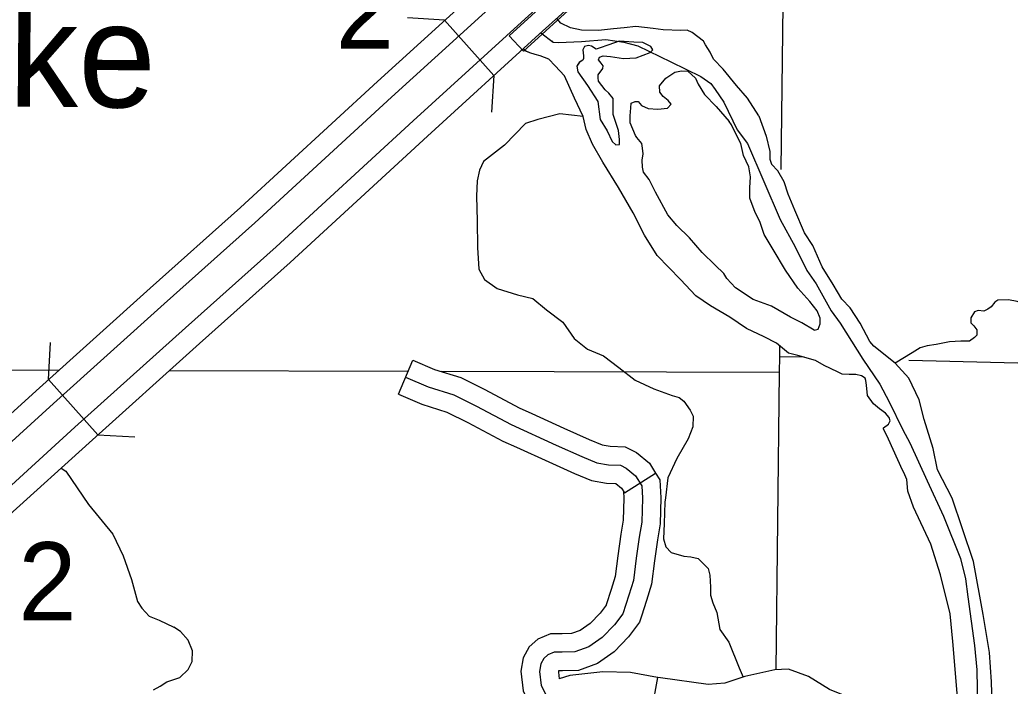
# Model space of a CAD drawing. Extents: x 8749 to 11879, y 13275 to 15339.
# Drawn here: x 10252.7 to 10333, y 13840.7 to 13894.7 of the extents above; entities that cross this region are included whole.
import ezdxf

# ---------------------------------------------------------------- set-up
doc = ezdxf.new("R2010")
doc.units = 0
for name, color, linetype in [('Level 19', 7, 'Continuous'), ('Level 2', 7, 'Continuous'), ('Level 35', 7, 'Continuous'), ('Level 37', 7, 'Continuous'), ('Level 39', 7, 'Continuous'), ('Level 4', 7, 'Continuous'), ('Level 45', 7, 'Continuous'), ('Level 5', 7, 'Continuous'), ('Level 9', 7, 'Continuous')]:
    doc.layers.add(name, color=color, linetype=linetype)

msp = doc.modelspace()

# ---------------------------------------------------------------- linework, layer by layer
at = {"layer": 'Level 19'}
msp.add_line((10293.525, 13892.125), (10292.381, 13893.383), dxfattribs=at)
for points in [[(10292.381, 13893.383), (10379.95, 13973.091)], [(10381.087, 13971.827), (10293.525, 13892.125)], [(10297.67, 13901.884), (10296.529, 13903.145), (10290.778, 13897.94), (10281.704, 13889.663), (10270.608, 13879.473), (10263.266, 13872.928), (10254.301, 13864.855), (10247.825, 13858.989), (10233.593, 13845.826)], [(10234.747, 13844.578), (10248.973, 13857.735), (10255.44, 13863.594), (10264.4, 13871.662), (10271.748, 13878.213), (10282.851, 13888.409), (10291.921, 13896.682), (10297.67, 13901.884)], [(10300.561, 13898.676), (10299.414, 13899.956), (10293.669, 13894.758), (10284.607, 13886.491), (10273.493, 13876.285), (10266.135, 13869.726), (10257.183, 13861.664), (10250.729, 13855.817), (10236.513, 13842.669)], [(10237.667, 13841.421), (10251.877, 13854.563), (10258.323, 13860.402), (10267.27, 13868.46), (10274.633, 13875.024), (10285.755, 13885.237), (10294.812, 13893.5), (10300.555, 13898.696)]]:
    msp.add_lwpolyline(points, dxfattribs=at)
at = {"layer": 'Level 2'}
for points in [[(10294.95, 13893.624), (10295.95, 13892.874), (10296.381, 13892.841), (10298.251, 13892.907), (10300.204, 13893.072), (10301.677, 13892.857), (10302.803, 13892.559), (10305.468, 13891.269), (10307.918, 13890.094), (10308.729, 13889.515), (10309.06, 13889.035), (10309.771, 13888.009), (10310.864, 13885.759), (10311.691, 13884.666), (10314.346, 13878.492)], [(10295.825, 13892.968), (10295.95, 13892.874), (10296.381, 13892.841), (10298.251, 13892.907), (10300.204, 13893.072), (10301.677, 13892.857), (10302.803, 13892.559), (10305.468, 13891.269), (10307.918, 13890.094), (10308.729, 13889.515), (10309.06, 13889.035), (10309.771, 13888.009), (10310.864, 13885.759), (10311.691, 13884.666), (10314.346, 13878.492)], [(10314.346, 13878.492), (10315.558, 13876.278), (10316.514, 13874.366), (10317.261, 13873.291), (10318.487, 13871.11), (10319.204, 13870.094), (10321.051, 13867.191), (10322.411, 13865.145), (10323.187, 13863.734), (10324.281, 13861.468), (10324.852, 13860.391), (10326.247, 13857.328), (10327.578, 13854.452), (10328.961, 13851.043), (10329.365, 13849.387), (10329.566, 13847.933), (10330.105, 13843.991), (10330.276, 13842.014), (10330.333, 13838.896)], [(10314.346, 13878.492), (10315.558, 13876.278), (10316.514, 13874.366), (10317.261, 13873.291), (10318.487, 13871.11), (10319.204, 13870.094), (10321.051, 13867.191), (10322.411, 13865.145), (10323.187, 13863.734), (10324.281, 13861.468), (10324.852, 13860.391), (10326.247, 13857.328), (10327.578, 13854.452), (10328.961, 13851.043), (10329.365, 13849.387), (10329.566, 13847.933), (10330.105, 13843.991), (10330.276, 13842.014), (10330.333, 13838.896)]]:
    msp.add_lwpolyline(points, dxfattribs=at)
at = {"layer": 'Level 35'}
for points in [[(10298.365, 13886.829), (10296.493, 13887.048), (10294.692, 13886.607), (10293.691, 13886.287), (10292.01, 13884.524), (10290.289, 13883.202), (10289.969, 13882.481), (10289.769, 13881.64), (10289.729, 13880.398), (10289.769, 13878.395), (10289.809, 13876.231), (10289.929, 13874.469), (10290.369, 13873.627), (10291.41, 13872.906), (10293.051, 13872.385), (10294.292, 13872.105), (10295.412, 13871.184), (10296.733, 13870.182), (10297.653, 13868.86), (10298.734, 13867.979), (10300.015, 13867.458), (10301.255, 13866.496), (10302.597, 13865.481)], [(10332.849, 13871.99), (10331.981, 13871.972), (10331.731, 13871.797), (10331.456, 13871.423), (10331.182, 13871.223), (10330.857, 13871.073), (10330.383, 13871.123), (10330.083, 13871.023), (10329.808, 13870.523), (10329.808, 13870.123), (10330.033, 13869.873), (10330.283, 13869.548), (10330.283, 13869.124), (10330.083, 13868.949), (10329.684, 13868.649), (10328.985, 13868.649), (10328.061, 13868.574), (10326.987, 13868.374), (10326.263, 13868.274), (10325.689, 13868.099), (10325.04, 13867.699), (10323.667, 13866.847)], [(10335.446, 13869.109), (10335.296, 13869.866), (10335.296, 13870.216), (10335.221, 13870.69), (10334.872, 13871.065), (10334.572, 13871.365), (10334.272, 13871.615), (10333.548, 13871.865), (10332.849, 13871.99)], [(10302.597, 13865.481), (10304.099, 13864.785), (10305.598, 13864.239), (10306.144, 13864.075), (10306.525, 13863.775), (10307.043, 13863.039), (10307.288, 13862.575), (10307.261, 13861.702), (10306.879, 13860.72), (10305.953, 13859.137), (10305.249, 13857.558), (10305.05, 13855.948), (10304.995, 13855.593), (10304.931, 13853.861), (10304.891, 13852.629), (10305.081, 13851.989), (10305.517, 13851.525), (10306.525, 13851.225), (10307.097, 13851.171), (10307.697, 13851.034), (10308.079, 13850.652), (10308.515, 13850.216), (10308.651, 13849.67), (10308.706, 13848.715), (10308.706, 13848.061), (10308.896, 13847.433), (10309.196, 13846.658), (10309.441, 13845.267), (10310.177, 13844.257), (10311.022, 13842.184), (10311.342, 13841.427)], [(10256.059, 13858.352), (10256.439, 13858.095), (10258.28, 13855.411), (10260.241, 13853.007), (10261.081, 13851.245), (10261.762, 13849.322), (10262.242, 13847.559), (10262.602, 13846.998), (10263.202, 13846.357), (10264.003, 13846.037), (10265.204, 13845.476)], [(10263.535, 13840.394), (10264.081, 13840.694), (10264.626, 13841.049), (10265.689, 13841.404), (10266.343, 13842.031), (10266.67, 13842.686), (10266.697, 13843.559), (10266.343, 13844.405), (10265.743, 13845.114), (10265.204, 13845.476)]]:
    msp.add_lwpolyline(points, dxfattribs=at)
at = {"layer": 'Level 39'}
for p, q in [((10287.136, 13894.655), (10284.141, 13894.828)), ((10291.126, 13890.174), (10287.136, 13894.655)), ((10291.126, 13890.174), (10290.953, 13887.179)), ((10255.032, 13865.524), (10255.193, 13868.519)), ((10255.032, 13865.524), (10259.042, 13861.06)), ((10259.042, 13861.06), (10262.038, 13860.9))]:
    msp.add_line(p, q, dxfattribs=at)
at = {"layer": 'Level 4'}
for points in [[(10314.739, 13911.435), (10314.398, 13882.543)], [(10314.281, 13868.287), (10314.277, 13867.41), (10314.27, 13866.1), (10313.992, 13842.024)]]:
    msp.add_lwpolyline(points, dxfattribs=at)
at = {"layer": 'Level 45'}
for p, q in [((10283.395, 13864.345), (10284.572, 13867.104)), ((10301.711, 13856.351), (10304.247, 13857.955)), ((10304.412, 13841.403), (10303.869, 13838.452))]:
    msp.add_line(p, q, dxfattribs=at)
for points in [[(10284.572, 13867.104), (10286.336, 13866.351), (10288.455, 13865.69), (10290.411, 13864.711), (10293.191, 13863.239), (10294.216, 13862.771)], [(10283.984, 13865.725), (10285.816, 13864.942), (10287.892, 13864.294), (10289.725, 13863.377), (10292.528, 13861.893), (10296.194, 13860.22), (10298.269, 13859.303), (10299.482, 13858.79), (10300.425, 13858.628), (10301.396, 13858.601), (10301.854, 13858.358), (10302.609, 13857.738), (10303.121, 13856.928), (10303.175, 13855.93), (10303.121, 13853.987), (10302.905, 13852.773), (10302.663, 13851.046), (10302.447, 13849.26), (10302.069, 13848.073), (10301.584, 13846.562), (10300.91, 13845.645), (10299.913, 13844.619), (10298.835, 13843.864), (10297.703, 13843.459), (10296.679, 13843.432), (10296.032, 13843.432), (10295.52, 13843.216), (10295.196, 13842.92), (10294.954, 13842.488), (10294.846, 13841.867), (10294.981, 13840.734), (10295.613, 13839.466)], [(10283.395, 13864.345), (10285.297, 13863.533), (10287.329, 13862.899), (10289.038, 13862.043), (10291.865, 13860.547), (10292.971, 13860.042)], [(10294.216, 13862.771), (10296.808, 13861.589), (10298.864, 13860.68), (10299.906, 13860.239), (10300.574, 13860.125), (10301.788, 13860.091), (10302.69, 13859.613), (10303.747, 13858.743), (10304.247, 13857.955)], [(10292.971, 13860.042), (10295.579, 13858.852), (10297.674, 13857.926), (10299.058, 13857.341), (10300.277, 13857.132), (10301.003, 13857.112), (10301.018, 13857.104), (10301.47, 13856.732), (10301.711, 13856.351)], [(10304.247, 13857.955), (10304.597, 13857.4), (10304.676, 13855.95), (10304.617, 13853.835), (10304.387, 13852.538), (10304.15, 13850.852), (10303.919, 13848.94), (10303.498, 13847.617), (10303.091, 13846.348)], [(10301.644, 13856.457), (10301.673, 13855.91), (10301.624, 13854.14), (10301.423, 13853.009), (10301.175, 13851.241), (10300.974, 13849.58), (10300.641, 13848.53), (10300.235, 13847.266)], [(10300.235, 13847.266), (10300.231, 13847.253), (10299.763, 13846.616), (10298.936, 13845.767), (10298.14, 13845.208), (10297.424, 13844.952), (10296.659, 13844.932), (10295.729, 13844.932), (10294.697, 13844.498), (10294.006, 13843.863), (10293.52, 13842.998), (10293.33, 13841.908), (10293.522, 13840.298), (10293.738, 13839.865)], [(10303.091, 13846.348), (10302.938, 13845.871), (10302.058, 13844.673), (10300.89, 13843.472), (10299.53, 13842.52), (10297.982, 13841.966), (10296.698, 13841.932), (10296.38, 13841.932), (10296.361, 13841.827), (10296.426, 13841.279)], [(10304.412, 13841.403), (10302.2, 13841.81), (10299.959, 13841.84), (10297.304, 13841.545), (10296.426, 13841.279)], [(10314.442, 13842.042), (10313.905, 13842.021), (10312.929, 13841.8), (10311.485, 13841.46), (10309.869, 13840.929), (10308.513, 13840.822), (10304.638, 13841.361), (10304.413, 13841.403)], [(10324.659, 13839.378), (10320.877, 13839.696), (10319.482, 13839.952), (10318.346, 13840.411), (10316.648, 13841.48), (10315.005, 13842.065), (10314.442, 13842.042)]]:
    msp.add_lwpolyline(points, dxfattribs=at)
at = {"layer": 'Level 5'}
msp.add_line((10314.277, 13867.41), (10316.286, 13867.36), dxfattribs=at)
for points in [[(10255.875, 13866.273), (10208.843, 13866.412)], [(10324.762, 13867.112), (10367.851, 13866.039)], [(10284.182, 13866.189), (10264.812, 13866.246)], [(10314.27, 13866.1), (10286.882, 13866.181)]]:
    msp.add_lwpolyline(points, dxfattribs=at)
at = {"layer": 'Level 9'}
for points in [[(10302.643, 13894.125), (10301.706, 13894.011), (10300.82, 13893.935), (10299.605, 13893.808), (10298.239, 13893.834), (10297.353, 13894.011), (10296.568, 13894.391), (10296.229, 13894.781)], [(10302.643, 13894.125), (10301.706, 13894.011), (10300.82, 13893.935), (10299.605, 13893.808), (10298.239, 13893.834), (10297.353, 13894.011), (10296.568, 13894.391), (10296.323, 13894.673)], [(10312.616, 13886.905), (10311.704, 13888.323), (10310.793, 13889.362), (10309.73, 13890.679), (10308.945, 13891.49), (10308.667, 13892.048), (10308.287, 13892.656), (10308.136, 13892.934), (10307.68, 13893.289), (10307.199, 13893.644), (10306.794, 13893.846), (10306.288, 13893.821), (10304.845, 13893.872), (10304.035, 13893.973), (10302.643, 13894.125)], [(10312.616, 13886.905), (10311.704, 13888.323), (10310.793, 13889.362), (10309.73, 13890.679), (10308.945, 13891.49), (10308.667, 13892.048), (10308.287, 13892.656), (10308.136, 13892.934), (10307.68, 13893.289), (10307.199, 13893.644), (10306.794, 13893.846), (10306.288, 13893.821), (10304.845, 13893.872), (10304.035, 13893.973), (10302.643, 13894.125)], [(10298.087, 13891.262), (10297.859, 13890.907), (10297.935, 13890.451), (10298.72, 13889.362), (10299.555, 13888.045), (10299.757, 13886.601), (10300.314, 13885.688), (10300.719, 13884.802), (10301.023, 13884.548), (10301.327, 13884.574), (10301.327, 13884.979), (10301.225, 13885.714), (10300.795, 13887.006), (10300.795, 13887.918), (10300.795, 13888.298), (10300.466, 13888.729), (10300.162, 13889.007), (10299.605, 13889.691), (10299.58, 13889.97), (10299.58, 13890.223), (10299.96, 13890.73), (10299.985, 13890.933), (10299.833, 13891.161), (10299.605, 13891.439), (10299.707, 13891.642), (10299.985, 13891.769), (10300.593, 13891.693), (10301.656, 13891.541), (10302.668, 13891.591), (10303.807, 13892.022), (10304.01, 13892.25), (10303.858, 13892.504), (10303.2, 13892.833), (10302.491, 13892.858), (10301.301, 13892.934), (10300.441, 13892.656), (10299.681, 13892.377), (10299.428, 13892.301), (10299.049, 13892.529), (10298.796, 13892.58), (10298.492, 13892.504), (10298.34, 13892.25), (10298.391, 13891.769), (10298.391, 13891.541), (10298.34, 13891.414), (10298.036, 13891.211)], [(10298.068, 13891.233), (10297.859, 13890.907), (10297.935, 13890.451), (10298.72, 13889.362), (10299.555, 13888.045), (10299.757, 13886.601), (10300.314, 13885.688), (10300.719, 13884.802), (10301.023, 13884.548), (10301.327, 13884.574), (10301.327, 13884.979), (10301.225, 13885.714), (10300.795, 13887.006), (10300.795, 13887.918), (10300.795, 13888.298), (10300.466, 13888.729), (10300.162, 13889.007), (10299.605, 13889.691), (10299.58, 13889.97), (10299.58, 13890.223), (10299.96, 13890.73), (10299.985, 13890.933), (10299.833, 13891.161), (10299.605, 13891.439), (10299.707, 13891.642), (10299.985, 13891.769), (10300.593, 13891.693), (10301.656, 13891.541), (10302.668, 13891.591), (10303.807, 13892.022), (10304.01, 13892.25), (10303.858, 13892.504), (10303.2, 13892.833), (10302.491, 13892.858), (10301.301, 13892.934), (10300.441, 13892.656), (10299.681, 13892.377), (10299.428, 13892.301), (10299.049, 13892.529), (10298.796, 13892.58), (10298.492, 13892.504), (10298.34, 13892.25), (10298.391, 13891.769), (10298.391, 13891.541), (10298.34, 13891.414), (10298.068, 13891.233)], [(10296.112, 13890.958), (10295.581, 13891.49), (10294.898, 13891.744), (10294.493, 13891.87), (10294.037, 13891.997), (10293.708, 13892.149), (10293.522, 13892.322)], [(10296.112, 13890.958), (10295.581, 13891.49), (10294.898, 13891.744), (10294.493, 13891.87), (10294.037, 13891.997), (10293.604, 13892.197)], [(10298.365, 13886.829), (10297.682, 13888.323), (10296.872, 13890.147), (10296.112, 13890.958)], [(10298.365, 13886.829), (10297.682, 13888.323), (10296.872, 13890.147), (10296.112, 13890.958)], [(10302.263, 13887.918), (10302.592, 13888.045), (10302.845, 13888.045), (10303.098, 13887.741), (10303.655, 13887.487), (10304.415, 13887.437), (10305.199, 13887.513), (10305.503, 13887.842), (10305.25, 13888.146), (10304.87, 13888.45), (10304.592, 13888.805), (10304.567, 13889.337), (10305.073, 13889.945), (10305.807, 13890.426), (10306.338, 13890.527), (10306.87, 13890.502), (10307.477, 13889.945), (10307.705, 13889.463), (10308.211, 13888.627), (10309.148, 13887.639), (10310.211, 13886.423)], [(10302.263, 13887.918), (10302.592, 13888.045), (10302.845, 13888.045), (10303.098, 13887.741), (10303.655, 13887.487), (10304.415, 13887.437), (10305.199, 13887.513), (10305.503, 13887.842), (10305.25, 13888.146), (10304.87, 13888.45), (10304.592, 13888.805), (10304.567, 13889.337), (10305.073, 13889.945), (10305.807, 13890.426), (10306.338, 13890.527), (10306.87, 13890.502), (10307.477, 13889.945), (10307.705, 13889.463), (10308.211, 13888.627), (10309.148, 13887.639), (10310.211, 13886.423)], [(10302.187, 13886.905), (10302.238, 13887.538), (10302.263, 13887.918)], [(10302.187, 13886.905), (10302.238, 13887.538), (10302.263, 13887.918)], [(10303.349, 13877.214), (10302.438, 13879.038), (10301.248, 13881.09), (10299.96, 13883.13), (10299.125, 13884.599), (10298.618, 13885.79), (10298.365, 13886.829)], [(10303.349, 13877.214), (10302.438, 13879.038), (10301.248, 13881.09), (10299.96, 13883.13), (10299.125, 13884.599), (10298.618, 13885.79), (10298.365, 13886.829)], [(10302.729, 13885.138), (10302.618, 13885.308), (10302.187, 13886.322), (10302.187, 13886.905)], [(10302.729, 13885.138), (10302.618, 13885.308), (10302.187, 13886.322), (10302.187, 13886.905)], [(10312.307, 13879.074), (10311.882, 13880.216), (10311.882, 13881.052), (10311.932, 13881.964), (10311.806, 13882.75), (10311.375, 13883.687), (10311.148, 13884.65), (10310.768, 13885.384), (10310.388, 13886.17), (10310.211, 13886.423)], [(10312.307, 13879.074), (10311.882, 13880.216), (10311.882, 13881.052), (10311.932, 13881.964), (10311.806, 13882.75), (10311.375, 13883.687), (10311.148, 13884.65), (10310.768, 13885.384), (10310.388, 13886.17), (10310.211, 13886.423)], [(10312.616, 13886.905), (10313.198, 13885.258), (10313.502, 13884.016), (10313.502, 13883.383), (10313.628, 13882.978), (10314.157, 13882.433)], [(10312.616, 13886.905), (10313.198, 13885.258), (10313.502, 13884.016), (10313.502, 13883.383), (10313.628, 13882.978), (10314.157, 13882.433)], [(10303.723, 13881.732), (10303.276, 13882.344), (10303.174, 13882.724), (10303.149, 13883.307), (10303.225, 13883.814), (10303.174, 13884.27), (10303.124, 13884.65), (10302.729, 13885.138)], [(10303.723, 13881.732), (10303.276, 13882.344), (10303.174, 13882.724), (10303.149, 13883.307), (10303.225, 13883.814), (10303.174, 13884.27), (10303.124, 13884.65), (10302.729, 13885.138)], [(10320.832, 13870.09), (10320.029, 13871.336), (10319.346, 13872.046), (10318.637, 13873.236), (10317.751, 13874.655), (10316.992, 13876.378), (10316.309, 13877.417), (10315.524, 13879.241), (10314.992, 13880.558), (10314.663, 13881.546), (10314.157, 13882.433)], [(10320.832, 13870.09), (10320.029, 13871.336), (10319.346, 13872.046), (10318.637, 13873.236), (10317.751, 13874.655), (10316.992, 13876.378), (10316.309, 13877.417), (10315.524, 13879.241), (10314.992, 13880.558), (10314.663, 13881.546), (10314.157, 13882.433)], [(10305.245, 13878.871), (10304.235, 13880.71), (10303.723, 13881.732)], [(10305.245, 13878.871), (10304.235, 13880.71), (10303.723, 13881.732)], [(10317.091, 13869.522), (10316.104, 13870.13), (10315.192, 13870.586), (10313.648, 13871.473), (10312.155, 13872.005), (10310.712, 13872.968), (10310.029, 13873.703), (10309.776, 13874.133), (10309.067, 13874.792), (10308.029, 13875.831), (10306.992, 13877.021), (10305.954, 13878.01), (10305.245, 13878.871)], [(10317.091, 13869.522), (10316.104, 13870.13), (10315.192, 13870.586), (10313.648, 13871.473), (10312.155, 13872.005), (10310.712, 13872.968), (10310.029, 13873.703), (10309.776, 13874.133), (10309.067, 13874.792), (10308.029, 13875.831), (10306.992, 13877.021), (10305.954, 13878.01), (10305.245, 13878.871)], [(10317.091, 13869.522), (10317.42, 13869.624), (10317.597, 13870.054), (10317.597, 13870.51), (10317.344, 13871.093), (10316.736, 13871.853), (10315.775, 13872.943), (10314.787, 13874.387), (10313.775, 13876.059), (10313.041, 13877.275), (10312.687, 13878.339), (10312.307, 13879.074)], [(10317.091, 13869.522), (10317.42, 13869.624), (10317.597, 13870.054), (10317.597, 13870.51), (10317.344, 13871.093), (10316.736, 13871.853), (10315.775, 13872.943), (10314.787, 13874.387), (10313.775, 13876.059), (10313.041, 13877.275), (10312.687, 13878.339), (10312.307, 13879.074)], [(10315.01, 13867.658), (10314.053, 13868.484), (10313.041, 13868.99), (10311.624, 13869.674), (10310.257, 13870.586), (10308.687, 13871.498), (10307.498, 13872.309), (10306.257, 13873.627), (10304.384, 13875.577), (10303.349, 13877.214)], [(10315.01, 13867.658), (10314.053, 13868.484), (10313.041, 13868.99), (10311.624, 13869.674), (10310.257, 13870.586), (10308.687, 13871.498), (10307.498, 13872.309), (10306.257, 13873.627), (10304.384, 13875.577), (10303.349, 13877.214)], [(10327.084, 13858.226), (10326.73, 13859.956), (10326.021, 13862.287), (10325.616, 13863.883), (10324.781, 13865.631), (10323.667, 13866.847), (10321.946, 13868.24), (10321.617, 13868.62), (10320.832, 13870.09)], [(10327.084, 13858.226), (10326.73, 13859.956), (10326.021, 13862.287), (10325.616, 13863.883), (10324.781, 13865.631), (10323.667, 13866.847), (10321.946, 13868.24), (10321.617, 13868.62), (10320.832, 13870.09)], [(10324.249, 13858.2), (10323.135, 13860.691), (10322.705, 13861.527), (10322.73, 13861.628), (10323.11, 13861.907), (10323.262, 13862.185), (10323.186, 13862.464), (10322.882, 13862.819), (10322.401, 13863.148), (10321.895, 13863.553), (10321.414, 13864.238), (10321.338, 13865.074), (10321.288, 13865.454), (10321.237, 13865.631), (10320.933, 13865.834), (10320.478, 13865.935), (10319.946, 13865.935), (10319.364, 13865.96), (10318.984, 13866.163), (10317.921, 13866.67), (10317.212, 13867.075), (10315.77, 13867.48), (10315.01, 13867.658)], [(10324.249, 13858.2), (10323.135, 13860.691), (10322.705, 13861.527), (10322.73, 13861.628), (10323.11, 13861.907), (10323.262, 13862.185), (10323.186, 13862.464), (10322.882, 13862.819), (10322.401, 13863.148), (10321.895, 13863.553), (10321.414, 13864.238), (10321.338, 13865.074), (10321.288, 13865.454), (10321.237, 13865.631), (10320.933, 13865.834), (10320.478, 13865.935), (10319.946, 13865.935), (10319.364, 13865.96), (10318.984, 13866.163), (10317.921, 13866.67), (10317.212, 13867.075), (10315.77, 13867.48), (10315.01, 13867.658)], [(10328.603, 13841.097), (10328.35, 13844.317), (10328.122, 13846.546), (10327.337, 13849.713), (10326.552, 13852.196), (10325.16, 13855.185), (10324.679, 13856.477), (10324.603, 13857.44), (10324.376, 13857.998), (10324.249, 13858.2)], [(10328.603, 13841.097), (10328.35, 13844.317), (10328.122, 13846.546), (10327.337, 13849.713), (10326.552, 13852.196), (10325.16, 13855.185), (10324.679, 13856.477), (10324.603, 13857.44), (10324.376, 13857.998), (10324.249, 13858.2)], [(10331.463, 13841.046), (10331.311, 13843.405), (10330.805, 13846.496), (10330.02, 13850.777), (10329.134, 13853.437), (10328.274, 13855.92), (10327.084, 13858.226)], [(10331.463, 13841.046), (10331.311, 13843.405), (10330.805, 13846.496), (10330.02, 13850.777), (10329.134, 13853.437), (10328.274, 13855.92), (10327.084, 13858.226)], [(10329.261, 13827.712), (10329.109, 13832.103), (10329.134, 13834.788), (10328.856, 13838.158), (10328.603, 13841.097)], [(10329.261, 13827.712), (10329.109, 13832.103), (10329.134, 13834.788), (10328.856, 13838.158), (10328.603, 13841.097)], [(10332.273, 13827.738), (10332.273, 13830.633), (10331.969, 13834.18), (10331.59, 13837.55), (10331.463, 13841.046)], [(10332.273, 13827.738), (10332.273, 13830.633), (10331.969, 13834.18), (10331.59, 13837.55), (10331.463, 13841.046)]]:
    msp.add_lwpolyline(points, dxfattribs=at)

# ---------------------------------------------------------------- texts
at = {"layer": 'Level 35'}
msp.add_text('Lake', height=8.448, rotation=359.5554, dxfattribs=at).set_placement((10239.21, 13887.745))
at = {"layer": 'Level 37'}
for p in [(10278.319, 13892.347), (10252.593, 13846.015)]:
    msp.add_text('2', height=6.336, dxfattribs=at).set_placement(p)

doc.saveas('drawing.dxf')
